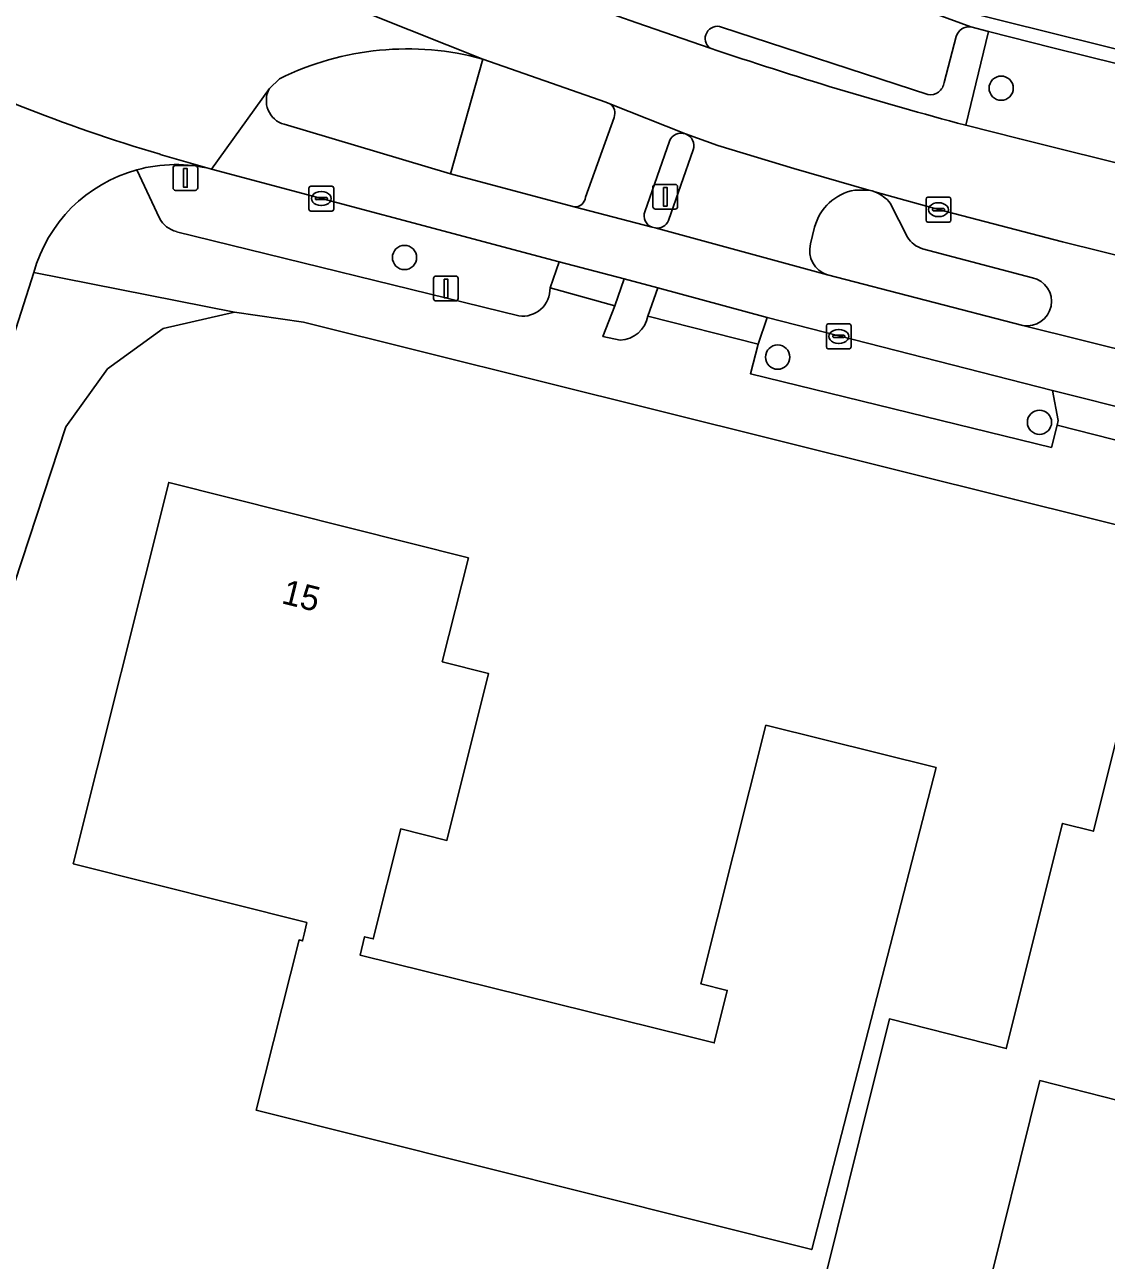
# Model space of a CAD drawing. Extents: x 161139 to 161601, y 381708 to 382245.
# Drawn here: x 161378.61 to 161422.21, y 382147.44 to 382197.24 of the extents above; entities that cross this region are included whole.
import ezdxf

# ---------------------------------------------------------------- set-up
doc = ezdxf.new("R2010")
doc.units = 0
for name, color, linetype in [('IMGEO_Berm_groen', 7, 'Continuous'), ('IMGEO_Boom', 7, 'Continuous'), ('IMGEO_Erf', 7, 'Continuous'), ('IMGEO_Fietspad_gesloten', 7, 'Continuous'), ('IMGEO_Kolk', 7, 'Continuous'), ('IMGEO_Lichtmast', 7, 'Continuous'), ('IMGEO_Muur', 7, 'Continuous'), ('IMGEO_Pand', 7, 'Continuous'), ('IMGEO_Pand_nummerreeks', 7, 'Continuous'), ('IMGEO_Parkeervlak_open', 7, 'Continuous'), ('IMGEO_Rijbaan_lokaal_gesloten', 7, 'Continuous'), ('IMGEO_Rijbaan_lokaal_open', 7, 'Continuous'), ('IMGEO_Verkeersbordpaal', 7, 'Continuous'), ('IMGEO_Verkeerseiland_open', 7, 'Continuous'), ('IMGEO_Voetpad_open', 7, 'Continuous')]:
    doc.layers.add(name, color=color, linetype=linetype)

msp = doc.modelspace()

# ---------------------------------------------------------------- linework, layer by layer
at = {"layer": 'IMGEO_Berm_groen'}
for points in [[(161500, 382176.547), (161460.894, 382186.197), (161420.058, 382196.306), (161417.456, 382196.964), (161416.542, 382193.184), (161418.72, 382192.635), (161459.898, 382182.379), (161500, 382172.465), (161568.862, 382155.44)], [(161402.198, 382194.055), (161402.036, 382194.12), (161397.081, 382195.854), (161395.77, 382191.23), (161400.753, 382189.896)], [(161401.211, 382190.284), (161402.364, 382193.499)], [(161383.123, 382191.388), (161384.037, 382189.44)], [(161400.157, 382187.686), (161386.139, 382191.421)], [(161412.878, 382190.505), (161412.768, 382190.537), (161412.637, 382190.575), (161412.068, 382190.572)], [(161414.192, 382188.674), (161413.5, 382190.042)], [(161384.721, 382188.897), (161398.528, 382185.5)], [(161410.452, 382189.082), (161410.292, 382188.402)], [(161419.229, 382187.043), (161414.806, 382188.21)], [(161399.787, 382186.631), (161400.157, 382187.686)], [(161404.125, 382186.632), (161402.771, 382186.995), (161402.397, 382185.906), (161401.916, 382184.669), (161402.608, 382184.522)], [(161410.964, 382187.154), (161418.85, 382185.12)], [(161403.727, 382185.497), (161404.125, 382186.632)]]:
    msp.add_lwpolyline(points, dxfattribs=at)
msp.add_lwpolyline([(161408.543, 382185.44), (161408.169, 382184.367), (161407.86, 382183.171), (161419.997, 382180.199), (161420.225, 382181.103), (161420.271, 382181.292), (161420.035, 382182.5)], close=True, dxfattribs=at)
for centre, radius, start, end in [((161401.953, 382193.679), 0.449, 336.3718, 56.8753), ((161384.694, 382185.656), 5.944, 75.9283, 105.3255), ((161400.786, 382190.321), 0.427, 265.5581, 354.9818), ((161412.431, 382188.556), 2.048, 100.2227, 165.1313), ((161412.352, 382189.148), 1.455, 37.8839, 68.7901), ((161385.009, 382189.963), 1.104, 208.2546, 254.8561), ((161411.278, 382188.128), 1.024, 164.4866, 252.1149), ((161415.129, 382189.276), 1.114, 212.7057, 253.1376), ((161419.022, 382186.085), 0.98, 259.8686, 77.8326), ((161398.677, 382186.6), 1.11, 262.267, 1.6018), ((161402.57, 382185.695), 1.174, 271.8463, 350.2859)]:
    msp.add_arc(centre, radius, start, end, dxfattribs=at)
at = {"layer": 'IMGEO_Boom'}
for centre in [(161417.973, 382194.68), (161393.919, 382187.856), (161408.961, 382183.841), (161419.516, 382181.215)]:
    msp.add_circle(centre, 0.489, dxfattribs=at)
at = {"layer": 'IMGEO_Erf'}
msp.add_lwpolyline([(161553.295, 382144.911), (161544.61, 382147.101), (161500, 382158.072), (161477.956, 382163.494), (161457.897, 382168.303), (161418.52, 382178.097), (161389.844, 382185.251), (161387.058, 382185.651), (161384.186, 382184.996), (161381.949, 382183.375), (161380.259, 382181.034), (161377.586, 382172.934), (161374.321, 382163.969), (161372.26, 382158.835), (161369.98, 382153.637), (161365.084, 382143.565), (161365.175, 382143.293), (161389.855, 382127.317), (161408.789, 382114.947), (161450.498, 382088.211), (161500, 382056.07), (161523.437, 382040.853), (161561.628, 382099.383), (161581.409, 382129.761)], dxfattribs=at)
for points in [[(161410.333, 382147.872), (161387.933, 382153.493), (161389.667, 382160.348), (161389.809, 382160.312), (161389.869, 382160.579), (161389.977, 382161.049), (161380.562, 382163.42), (161384.415, 382178.79), (161396.492, 382175.746), (161395.44, 382171.566), (161397.305, 382171.088), (161395.629, 382164.363), (161393.766, 382164.828), (161392.661, 382160.393), (161392.312, 382160.48), (161392.128, 382159.743), (161405.328, 382156.469), (161406.405, 382156.202), (161406.93, 382158.318), (161405.861, 382158.583), (161408.489, 382169.001), (161415.348, 382167.296)], [(161417.202, 382145.309), (161410.912, 382146.912), (161412.259, 382152.318), (161413.467, 382157.169), (161418.18, 382155.968), (161420.44, 382165.046), (161421.693, 382164.734), (161422.647, 382168.564), (161426.089, 382167.707), (161426.329, 382168.67), (161428.734, 382168.071), (161428.484, 382167.068), (161429.913, 382166.712), (161428.705, 382161.861), (161426.476, 382152.914), (161419.537, 382154.683)]]:
    msp.add_lwpolyline(points, close=True, dxfattribs=at)
at = {"layer": 'IMGEO_Fietspad_gesloten'}
for points in [[(161388.471, 382194.662), (161386.139, 382191.421), (161400.157, 382187.686), (161402.771, 382186.995), (161404.125, 382186.632), (161408.543, 382185.44), (161420.035, 382182.5), (161423.68, 382181.579), (161459.001, 382172.814), (161463.49, 382171.731), (161479.47, 382167.765), (161485.068, 382166.376)], [(161487.403, 382168.106), (161478.19, 382170.397), (161465.508, 382173.515), (161458.283, 382175.333), (161426.145, 382183.304), (161418.85, 382185.12), (161410.964, 382187.154), (161404.025, 382189.049), (161403.898, 382189.082), (161400.753, 382189.896), (161395.77, 382191.23), (161389.063, 382193.224)]]:
    msp.add_lwpolyline(points, dxfattribs=at)
msp.add_arc((161389.344, 382194.18), 0.997, 151.1111, 253.6412, dxfattribs=at)
at = {"layer": 'IMGEO_Kolk'}
for p, q in [((161390.14, 382190.73), (161390.992, 382190.73)), ((161390.065, 382189.804), (161390.065, 382190.656)), ((161390.324, 382190.224), (161390.324, 382190.236)), ((161390.762, 382190.187), (161390.364, 382190.187)), ((161390.367, 382190.273), (161390.765, 382190.273)), ((161390.553, 382190.51), (161390.578, 382190.51)), ((161390.808, 382190.236), (161390.808, 382190.224)), ((161391.066, 382190.656), (161391.066, 382189.804)), ((161414.944, 382189.358), (161414.944, 382190.21)), ((161415.019, 382190.284), (161415.871, 382190.284)), ((161415.945, 382190.21), (161415.945, 382189.358)), ((161390.992, 382189.73), (161390.14, 382189.73)), ((161390.576, 382189.95), (161390.551, 382189.95)), ((161415.203, 382189.778), (161415.203, 382189.79)), ((161415.641, 382189.741), (161415.243, 382189.741)), ((161415.246, 382189.827), (161415.644, 382189.827)), ((161415.432, 382190.064), (161415.457, 382190.064)), ((161415.687, 382189.79), (161415.687, 382189.778)), ((161415.871, 382189.284), (161415.019, 382189.284)), ((161415.455, 382189.504), (161415.43, 382189.504)), ((161410.925, 382184.25), (161410.925, 382185.102)), ((161411, 382185.176), (161411.852, 382185.176)), ((161411.227, 382184.719), (161411.625, 382184.719)), ((161411.413, 382184.956), (161411.438, 382184.956)), ((161411.926, 382185.102), (161411.926, 382184.25)), ((161411.184, 382184.67), (161411.184, 382184.682)), ((161411.622, 382184.633), (161411.224, 382184.633)), ((161411.436, 382184.396), (161411.411, 382184.396)), ((161411.668, 382184.682), (161411.668, 382184.67)), ((161411.852, 382184.176), (161411, 382184.176))]:
    msp.add_line(p, q, dxfattribs=at)
for points in [[(161390.14, 382190.73), (161390.992, 382190.73)], [(161390.065, 382189.804), (161390.065, 382190.656)], [(161391.066, 382190.656), (161391.066, 382189.804)], [(161414.944, 382189.358), (161414.944, 382190.21)], [(161415.019, 382190.284), (161415.871, 382190.284)], [(161415.945, 382190.21), (161415.945, 382189.358)], [(161390.992, 382189.73), (161390.14, 382189.73)], [(161415.871, 382189.284), (161415.019, 382189.284)], [(161410.925, 382184.25), (161410.925, 382185.102)], [(161411, 382185.176), (161411.852, 382185.176)], [(161411.926, 382185.102), (161411.926, 382184.25)], [(161411.852, 382184.176), (161411, 382184.176)]]:
    msp.add_lwpolyline(points, dxfattribs=at)
for centre, radius, start, end in [((161390.142, 382190.654), 0.0765, 91.552, 178.448), ((161390.142, 382190.654), 0.0765, 91.552, 178.448), ((161390.99, 382190.654), 0.0765, 1.552, 88.448), ((161390.99, 382190.654), 0.0765, 1.552, 88.448), ((161390.364, 382190.233), 0.0403, 85.8775, 175.7526), ((161390.361, 382190.223), 0.0366, 178.938, 274.7102), ((161390.765, 382190.23), 0.043, 264.8664, 352.4533), ((161390.769, 382190.235), 0.0386, 1.7309, 96.639), ((161415.021, 382190.208), 0.0765, 91.552, 178.448), ((161415.021, 382190.208), 0.0765, 91.552, 178.448), ((161415.869, 382190.208), 0.0765, 1.552, 88.448), ((161415.869, 382190.208), 0.0765, 1.552, 88.448), ((161390.142, 382189.806), 0.0765, 181.552, 268.448), ((161390.142, 382189.806), 0.0765, 181.552, 268.448), ((161390.99, 382189.806), 0.0765, 271.552, 358.448), ((161390.99, 382189.806), 0.0765, 271.552, 358.448), ((161415.243, 382189.787), 0.0403, 85.8775, 175.7526), ((161415.24, 382189.777), 0.0366, 178.938, 274.7102), ((161415.644, 382189.784), 0.043, 264.8664, 352.4533), ((161415.648, 382189.789), 0.0386, 1.7309, 96.639), ((161415.021, 382189.36), 0.0765, 181.552, 268.448), ((161415.021, 382189.36), 0.0765, 181.552, 268.448), ((161415.869, 382189.36), 0.0765, 271.552, 358.448), ((161415.869, 382189.36), 0.0765, 271.552, 358.448), ((161411.002, 382185.1), 0.0765, 91.552, 178.448), ((161411.002, 382185.1), 0.0765, 91.552, 178.448), ((161411.224, 382184.679), 0.0403, 85.8775, 175.7526), ((161411.629, 382184.681), 0.0386, 1.7309, 96.639), ((161411.85, 382185.1), 0.0765, 1.552, 88.448), ((161411.85, 382185.1), 0.0765, 1.552, 88.448), ((161411.002, 382184.252), 0.0765, 181.552, 268.448), ((161411.002, 382184.252), 0.0765, 181.552, 268.448), ((161411.221, 382184.669), 0.0366, 178.938, 274.7102), ((161411.625, 382184.676), 0.043, 264.8664, 352.4533), ((161411.85, 382184.252), 0.0765, 271.552, 358.448), ((161411.85, 382184.252), 0.0765, 271.552, 358.448)]:
    msp.add_arc(centre, radius, start, end, dxfattribs=at)
for centre, major_axis, ratio, start_param, end_param in [((161390.552, 382190.23), (-0.387, 0.002), 0.722429, 4.712389, 7.853982), ((161390.577, 382190.23), (-0.39, 0.002), 0.717154, 1.570796, 4.712389), ((161415.431, 382189.784), (-0.387, 0.002), 0.722429, 4.712389, 7.853982), ((161415.456, 382189.784), (-0.39, 0.002), 0.717154, 1.570796, 4.712389), ((161411.412, 382184.676), (-0.387, 0.002), 0.722429, 4.712389, 7.853982), ((161411.437, 382184.676), (-0.39, 0.002), 0.717154, 1.570796, 4.712389)]:
    msp.add_ellipse(centre, major_axis=major_axis, ratio=ratio, start_param=start_param, end_param=end_param, dxfattribs=at)
at = {"layer": 'IMGEO_Lichtmast'}
for p, q in [((161403.935, 382189.904), (161403.935, 382190.704)), ((161403.935, 382190.704), (161403.935, 382189.904)), ((161404.035, 382190.804), (161404.825, 382190.804)), ((161404.825, 382190.804), (161404.035, 382190.804)), ((161404.925, 382190.704), (161404.925, 382189.904)), ((161404.925, 382189.904), (161404.925, 382190.704)), ((161404.825, 382189.804), (161404.035, 382189.804)), ((161404.035, 382189.804), (161404.825, 382189.804)), ((161395.091, 382186.208), (161395.091, 382187.008)), ((161395.091, 382187.008), (161395.091, 382186.208)), ((161395.191, 382187.108), (161395.981, 382187.108)), ((161395.981, 382187.108), (161395.191, 382187.108)), ((161396.081, 382187.008), (161396.081, 382186.208)), ((161396.081, 382186.208), (161396.081, 382187.008)), ((161395.981, 382186.108), (161395.191, 382186.108)), ((161395.191, 382186.108), (161395.981, 382186.108))]:
    msp.add_line(p, q, dxfattribs=at)
for points in [[(161404.355, 382190.679), (161404.505, 382190.679), (161404.505, 382189.929), (161404.355, 382189.929), (161404.355, 382190.679)], [(161395.511, 382186.983), (161395.661, 382186.983), (161395.661, 382186.233), (161395.511, 382186.233), (161395.511, 382186.983)]]:
    msp.add_lwpolyline(points, dxfattribs=at)
for centre, start, end in [((161404.035, 382190.704), 90, 180), ((161404.035, 382190.704), 90, 180), ((161404.825, 382190.704), 0, 90), ((161404.825, 382190.704), 360, 90), ((161404.035, 382189.904), 180, 270), ((161404.035, 382189.904), 180, 270), ((161404.825, 382189.904), 270, 0), ((161404.825, 382189.904), 270, 0), ((161395.191, 382187.008), 90, 180), ((161395.191, 382187.008), 90, 180), ((161395.981, 382187.008), 0, 90), ((161395.981, 382187.008), 360, 90), ((161395.191, 382186.208), 180, 270), ((161395.191, 382186.208), 180, 270), ((161395.981, 382186.208), 270, 0), ((161395.981, 382186.208), 270, 0)]:
    msp.add_arc(centre, 0.1, start, end, dxfattribs=at)
at = {"layer": 'IMGEO_Muur'}
msp.add_lwpolyline([(161365.084, 382143.565), (161369.98, 382153.637), (161372.26, 382158.835), (161374.321, 382163.969), (161377.586, 382172.934), (161380.259, 382181.034), (161381.949, 382183.375), (161384.186, 382184.996), (161387.058, 382185.651), (161389.844, 382185.251), (161418.52, 382178.097)], dxfattribs=at)
at = {"layer": 'IMGEO_Pand'}
for points in [[(161405.328, 382156.469), (161392.128, 382159.743), (161392.312, 382160.48), (161392.661, 382160.393), (161393.766, 382164.828), (161395.629, 382164.363), (161397.305, 382171.088), (161395.44, 382171.566), (161396.492, 382175.746), (161384.415, 382178.79), (161380.562, 382163.42), (161389.977, 382161.049), (161389.869, 382160.579), (161389.809, 382160.312), (161389.667, 382160.348), (161387.933, 382153.493), (161410.333, 382147.872), (161415.348, 382167.296), (161408.489, 382169.001), (161405.861, 382158.583), (161406.93, 382158.318), (161406.405, 382156.202)], [(161428.705, 382161.861), (161429.913, 382166.712), (161428.484, 382167.068), (161428.734, 382168.071), (161426.329, 382168.67), (161426.089, 382167.707), (161422.647, 382168.564), (161421.693, 382164.734), (161420.44, 382165.046), (161418.18, 382155.968), (161413.467, 382157.169), (161412.259, 382152.318), (161410.912, 382146.912), (161417.202, 382145.309), (161419.537, 382154.683), (161426.476, 382152.914)]]:
    msp.add_lwpolyline(points, close=True, dxfattribs=at)
at = {"layer": 'IMGEO_Parkeervlak_open'}
for points in [[(161502.587, 382168.125), (161500, 382168.766), (161459.102, 382178.908), (161420.449, 382188.487), (161415.442, 382189.785), (161412.878, 382190.505)], [(161413.5, 382190.042), (161414.192, 382188.674)], [(161414.806, 382188.21), (161419.229, 382187.043)], [(161418.85, 382185.12), (161426.145, 382183.304)]]:
    msp.add_lwpolyline(points, dxfattribs=at)
for centre, radius, start, end in [((161412.352, 382189.148), 1.455, 37.8839, 68.7901), ((161415.129, 382189.276), 1.114, 212.7057, 253.1376), ((161419.022, 382186.085), 0.98, 259.8686, 77.8326)]:
    msp.add_arc(centre, radius, start, end, dxfattribs=at)
at = {"layer": 'IMGEO_Rijbaan_lokaal_gesloten'}
for points in [[(161562.018, 382161.64), (161415.973, 382197.911), (161384.398, 382213.493), (161381.617, 382214.866), (161356.708, 382243.113)], [(161374.664, 382217.069), (161378.836, 382213.986), (161381.705, 382212.177), (161383.113, 382211.438), (161385.647, 382210.252), (161389.368, 382208.652), (161392.021, 382207.47), (161392.131, 382207.421), (161400.173, 382203.726), (161402.655, 382202.572), (161402.834, 382202.489), (161404.051, 382201.98), (161404.678, 382201.717), (161413.629, 382198.305), (161416.752, 382197.147), (161417.456, 382196.964), (161420.058, 382196.306), (161460.894, 382186.197), (161500, 382176.547)], [(161397.081, 382195.854), (161389.691, 382198.806), (161385.013, 382201.164), (161379.73, 382204.16), (161371.295, 382209.7)], [(161371.295, 382209.7), (161379.73, 382204.16), (161385.013, 382201.164), (161389.691, 382198.806), (161397.081, 382195.854), (161402.036, 382194.12), (161402.198, 382194.055), (161405.248, 382192.835), (161406.546, 382192.371), (161409.616, 382191.449), (161412.637, 382190.575), (161412.768, 382190.537), (161412.878, 382190.505), (161415.442, 382189.785), (161420.449, 382188.487), (161459.102, 382178.908), (161500, 382168.766), (161502.587, 382168.125), (161571.771, 382151.019), (161574.719, 382150.267), (161575.117, 382154.078)], [(161406.237, 382196.29), (161403.28, 382197.317), (161402.517, 382197.586), (161398.032, 382199.282), (161395.274, 382200.396), (161393.735, 382201.033)], [(161384.063, 382192.014), (161386.139, 382191.421), (161388.471, 382194.662), (161388.88, 382195.063)], [(161568.862, 382155.44), (161500, 382172.465), (161459.898, 382182.379), (161418.72, 382192.635), (161416.542, 382193.184)]]:
    msp.add_lwpolyline(points, dxfattribs=at)
for centre, radius, start, end in [((161402.679, 382255.054), 65.731, 243.04218, 253.54772), ((161394.025, 382184.632), 11.631, 74.7652, 116.2532), ((161461.322, 382360.402), 173.11, 251.44538, 255.00826)]:
    msp.add_arc(centre, radius, start, end, dxfattribs=at)
at = {"layer": 'IMGEO_Rijbaan_lokaal_open'}
for points in [[(161386.139, 382191.421), (161384.063, 382192.014)], [(161375.689, 382176.983), (161378.971, 382187.245)]]:
    msp.add_lwpolyline(points, dxfattribs=at)
for centre, radius, start, end in [((161402.679, 382255.054), 65.731, 243.04218, 253.54772), ((161384.695, 382185.661), 5.939, 105.346, 164.5297), ((161384.694, 382185.656), 5.944, 75.9283, 105.3255)]:
    msp.add_arc(centre, radius, start, end, dxfattribs=at)
at = {"layer": 'IMGEO_Verkeersbordpaal'}
for p, q in [((161384.59, 382190.663), (161384.59, 382191.463)), ((161384.59, 382191.463), (161384.59, 382190.663)), ((161384.69, 382191.563), (161385.48, 382191.563)), ((161385.48, 382191.563), (161384.69, 382191.563)), ((161385.58, 382191.463), (161385.58, 382190.663)), ((161385.58, 382190.663), (161385.58, 382191.463)), ((161385.48, 382190.563), (161384.69, 382190.563)), ((161384.69, 382190.563), (161385.48, 382190.563))]:
    msp.add_line(p, q, dxfattribs=at)
msp.add_lwpolyline([(161385.01, 382191.438), (161385.16, 382191.438), (161385.16, 382190.688), (161385.01, 382190.688), (161385.01, 382191.438)], dxfattribs=at)
for centre, start, end in [((161384.69, 382191.463), 90, 180), ((161384.69, 382191.463), 90, 180), ((161385.48, 382191.463), 0, 90), ((161385.48, 382191.463), 360, 90), ((161384.69, 382190.663), 180, 270), ((161384.69, 382190.663), 180, 270), ((161385.48, 382190.663), 270, 0), ((161385.48, 382190.663), 270, 0)]:
    msp.add_arc(centre, 0.1, start, end, dxfattribs=at)
at = {"layer": 'IMGEO_Verkeerseiland_open'}
for points in [[(161415.009, 382194.421), (161406.697, 382197.146)], [(161416.157, 382196.766), (161415.674, 382194.913)], [(161416.542, 382193.184), (161417.456, 382196.964), (161416.752, 382197.147)], [(161389.063, 382193.224), (161395.77, 382191.23), (161397.081, 382195.854)], [(161388.88, 382195.063), (161388.471, 382194.662)], [(161404.599, 382192.547), (161403.606, 382189.703)], [(161404.555, 382189.347), (161405.556, 382192.197)], [(161403.898, 382189.082), (161404.025, 382189.049)]]:
    msp.add_lwpolyline(points, dxfattribs=at)
for centre, radius, start, end in [((161406.532, 382196.683), 0.491, 70.3528, 233.1415), ((161416.678, 382196.608), 0.544, 82.1598, 163.106), ((161394.025, 382184.632), 11.631, 74.7652, 116.2532), ((161461.322, 382360.402), 173.11, 251.44538, 255.00826), ((161415.108, 382194.983), 0.57, 259.9947, 352.9971), ((161389.344, 382194.18), 0.997, 151.1111, 253.6412), ((161405.073, 382192.355), 0.511, 69.9207, 157.9388), ((161405.072, 382192.357), 0.51, 341.767, 69.7717), ((161404.048, 382189.532), 0.474, 158.813, 251.5537), ((161404.114, 382189.511), 0.47, 259.0634, 339.6316)]:
    msp.add_arc(centre, radius, start, end, dxfattribs=at)
at = {"layer": 'IMGEO_Voetpad_open'}
for points in [[(161416.752, 382197.147), (161413.629, 382198.305)], [(161403.28, 382197.317), (161406.237, 382196.29)], [(161406.697, 382197.146), (161415.009, 382194.421)], [(161415.674, 382194.913), (161416.157, 382196.766)], [(161405.248, 382192.835), (161402.198, 382194.055)], [(161402.364, 382193.499), (161401.211, 382190.284)], [(161412.068, 382190.572), (161412.637, 382190.575), (161409.616, 382191.449), (161406.546, 382192.371), (161405.248, 382192.835)], [(161403.606, 382189.703), (161404.599, 382192.547)], [(161405.556, 382192.197), (161404.555, 382189.347)], [(161384.037, 382189.44), (161383.123, 382191.388)], [(161400.753, 382189.896), (161403.898, 382189.082)], [(161398.528, 382185.5), (161384.721, 382188.897)], [(161404.025, 382189.049), (161410.964, 382187.154)], [(161410.292, 382188.402), (161410.452, 382189.082)], [(161369.98, 382153.637), (161372.26, 382158.835), (161374.321, 382163.969), (161377.586, 382172.934), (161380.259, 382181.034), (161381.949, 382183.375), (161384.186, 382184.996), (161387.058, 382185.651), (161378.971, 382187.245), (161375.689, 382176.983)], [(161378.971, 382187.245), (161387.058, 382185.651), (161389.844, 382185.251), (161418.52, 382178.097), (161457.897, 382168.303), (161477.956, 382163.494), (161500, 382158.072), (161544.61, 382147.101), (161553.295, 382144.911), (161577.621, 382138.939), (161579.137, 382138.37), (161582.049, 382137.272), (161581.211, 382138.152), (161576.782, 382142.804)], [(161402.608, 382184.522), (161401.916, 382184.669), (161402.397, 382185.906), (161399.787, 382186.631)], [(161423.245, 382180.339), (161420.225, 382181.103), (161419.997, 382180.199), (161407.86, 382183.171), (161408.169, 382184.367), (161403.727, 382185.497)]]:
    msp.add_lwpolyline(points, dxfattribs=at)
for points in [[(161402.771, 382186.995), (161400.157, 382187.686), (161399.787, 382186.631), (161402.397, 382185.906)], [(161408.543, 382185.44), (161404.125, 382186.632), (161403.727, 382185.497), (161408.169, 382184.367)], [(161423.68, 382181.579), (161420.035, 382182.5), (161420.271, 382181.292), (161420.225, 382181.103), (161423.245, 382180.339)]]:
    msp.add_lwpolyline(points, close=True, dxfattribs=at)
for centre, radius, start, end in [((161406.532, 382196.683), 0.491, 70.3528, 233.1415), ((161416.678, 382196.608), 0.544, 82.1598, 163.106), ((161415.108, 382194.983), 0.57, 259.9947, 352.9971), ((161401.953, 382193.679), 0.449, 336.3718, 56.8753), ((161405.073, 382192.355), 0.511, 69.9207, 157.9388), ((161405.072, 382192.357), 0.51, 341.767, 69.7717), ((161384.695, 382185.661), 5.939, 105.346, 164.5297), ((161400.786, 382190.321), 0.427, 265.5581, 354.9818), ((161412.431, 382188.556), 2.048, 100.2227, 165.1313), ((161404.048, 382189.532), 0.474, 158.813, 251.5537), ((161385.009, 382189.963), 1.104, 208.2546, 254.8561), ((161404.114, 382189.511), 0.47, 259.0634, 339.6316), ((161411.278, 382188.128), 1.024, 164.4866, 252.1149), ((161398.677, 382186.6), 1.11, 262.267, 1.6018), ((161402.57, 382185.695), 1.174, 271.8463, 350.2859)]:
    msp.add_arc(centre, radius, start, end, dxfattribs=at)

# ---------------------------------------------------------------- texts
at = {"layer": 'IMGEO_Pand_nummerreeks'}
msp.add_text('15', height=1, rotation=346.015, dxfattribs=at).set_placement((161388.916, 382173.928))

doc.saveas('drawing.dxf')
